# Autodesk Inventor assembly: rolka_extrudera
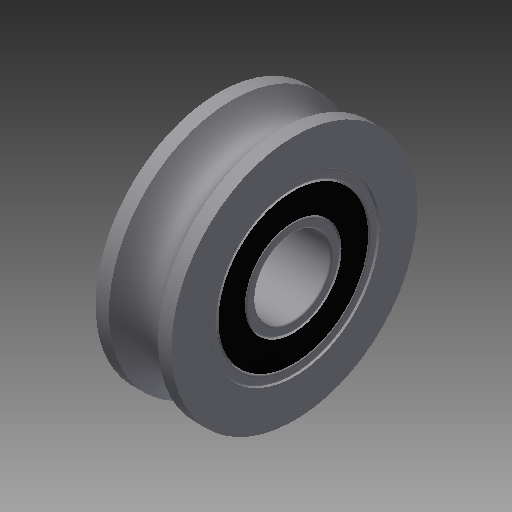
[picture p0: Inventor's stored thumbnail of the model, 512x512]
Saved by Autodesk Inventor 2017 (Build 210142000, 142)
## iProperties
Created: 2021-01
Part Number: rolka_extrudera
Document SubType Name: Assembly
Designer: WindowsX
Author: WindowsX
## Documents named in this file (3)
- C:\Users\WindowsX\Desktop\modele_3d\rolka_extrudera.iam
- C:\Users\WindowsX\Desktop\modele_3d\Rolka.ipt
- C:\Users\WindowsX\Desktop\modele_3d\684ZZ.ipt
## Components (2 placed, 2 different names)
1. Rolka:1 — Zestawiający:1, Zestawiający:2
2. 684ZZ:1 — Zestawiający:1, Zestawiający:2
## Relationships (2: Mate 2)
- Zestawiający:1 [Mate]: Rolka:1 ↔ 684ZZ:1
- Zestawiający:2 [Mate]: Rolka:1 ↔ 684ZZ:1
